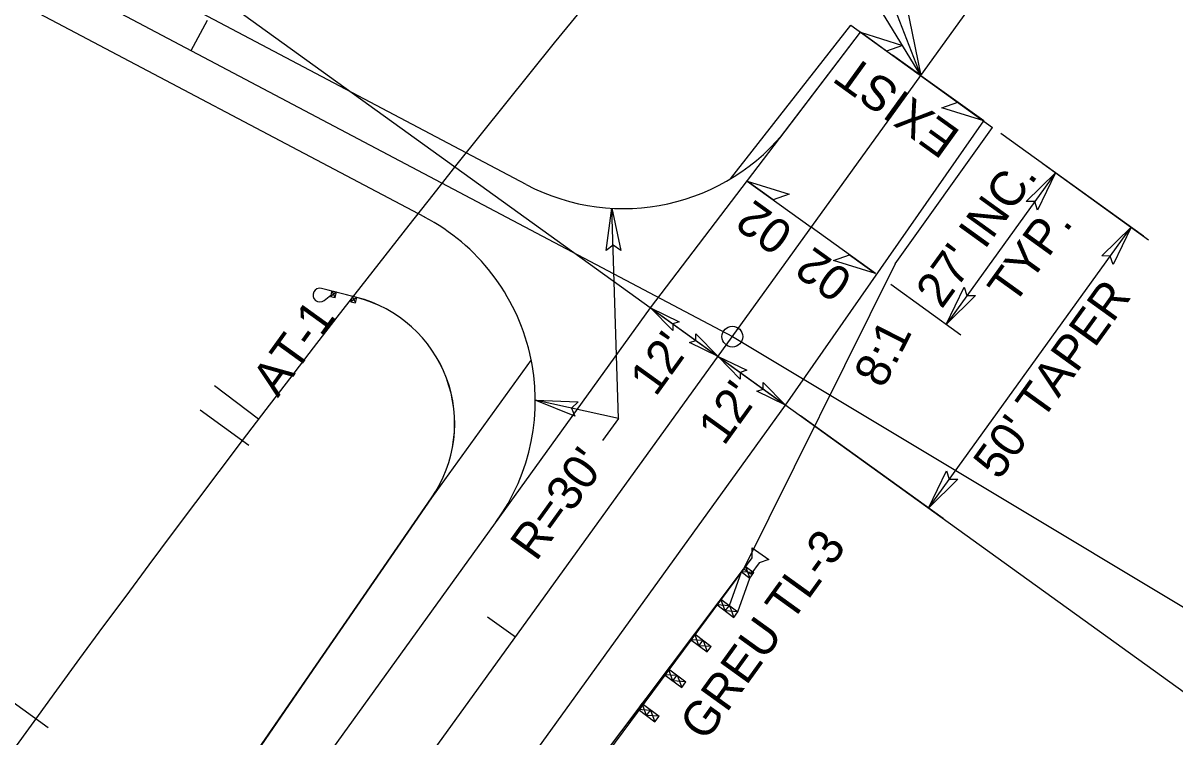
# Model space of a CAD drawing. Extents: x 2189281 to 2191267, y 386656 to 389012.
# Drawn here: x 2190394.2 to 2190560.4, y 388056.4 to 388159.5 of the extents above; entities that cross this region are included whole.
import ezdxf

# ---------------------------------------------------------------- set-up
doc = ezdxf.new("R2010")
doc.units = 0
for name, color, linetype in [('Prop Conc Shoulder Berm Gutter', 7, 'Continuous'), ('Prop Dimension', 7, 'Continuous'), ('Prop Dimension Text', 7, 'Continuous'), ('Prop DSN Text', 7, 'Continuous'), ('Prop EOT', 7, 'Continuous'), ('Prop Guardrail', 7, 'Continuous'), ('Prop Guardrail Anchor Unit CELL', 7, 'Continuous'), ('Prop Horizontal Alignment', 7, 'Continuous'), ('Prop Horizontal Alignment Station Label', 7, 'Continuous'), ('Prop Horizontal Alignment Tick Large', 7, 'Continuous'), ('Prop Horizontal Alignment Tick Small', 7, 'Continuous'), ('Prop Paved Shoulder', 7, 'Continuous'), ('Prop Superelevation  Arrow CELL', 7, 'Continuous'), ('Prop Superelevation Label', 7, 'Continuous'), ('Prop Terminator CELL', 7, 'Continuous'), ('Scratch_Level_5', 7, 'Continuous'), ('Scratch_Level_6', 7, 'Continuous')]:
    doc.layers.add(name, color=color, linetype=linetype)

msp = doc.modelspace()

# ---------------------------------------------------------------- linework, layer by layer
at = {"layer": 'Prop Conc Shoulder Berm Gutter'}
msp.add_line((2190437.14, 388067.73), (2190410.55, 388029.13), dxfattribs=at)
at = {"layer": 'Prop Dimension'}
for p, q in [((2190555.92, 388128.75), (2190535.33, 388143.6)), ((2190541.4, 388139.23), (2190556.63, 388128.24)), ((2190543.22, 388137.91), (2190527.43, 388116.01)), ((2190524.87, 388089.5), (2190554.12, 388130.05)), ((2190529.56, 388114.48), (2190519.46, 388121.76)), ((2190484.78, 388118.41), (2190504.24, 388104.37)), ((2190526.99, 388087.97), (2190506.41, 388102.81))]:
    msp.add_line(p, q, dxfattribs=at)
at = {"layer": 'Prop Dimension Text'}
for q in [(2190479.19, 388132.78), (2190468.12, 388105.07), (2190477.85, 388099.25)]:
    msp.add_line((2190480.16, 388102.45), q, dxfattribs=at)
at = {"layer": 'Prop DSN Text'}
msp.add_line((2190523.75, 388151.95), (2190443.96, 388359.41), dxfattribs=at)
at = {"layer": 'Prop EOT'}
for p, q in [((2190466.8, 388136.22), (2190376.83, 388183.79)), ((2190371.69, 388174.06), (2190452.14, 388131.53)), ((2190513.68, 388159.22), (2190534.13, 388144.46)), ((2190484.78, 388118.41), (2190515.08, 388158.2)), ((2190503.44, 388142.91), (2190515.08, 388158.2)), ((2190192.31, 387712.87), (2190484.78, 388118.41))]:
    msp.add_line(p, q, dxfattribs=at)
msp.add_lwpolyline([(2190181.76, 387658.83), (2190211.78, 387698.83), (2190504.24, 388104.37), (2190532.84, 388145.39)], dxfattribs=at)
for centre, start, end in [((2190480.83, 388162.74), 242.1321, 322.7007), ((2190438.12, 388105), 324.2018, 62.1321)]:
    msp.add_arc(centre, 30, start, end, dxfattribs=at)
at = {"layer": 'Prop Guardrail'}
msp.add_lwpolyline([(2190453.17, 388090.99), (2190411.02, 388029.82), (2190409.78, 388028.09)], dxfattribs=at)
msp.add_arc((2190437.67, 388101.68), 18.83, 325.3973, 75.5272, dxfattribs=at)
at = {"layer": 'Prop Guardrail Anchor Unit CELL'}
for p, q in [((2190438.95, 388120.79), (2190437.28, 388121.22)), ((2190438.75, 388120.84), (2190438.55, 388120.06)), ((2190438.75, 388120.84), (2190438.67, 388120.5)), ((2190438.75, 388120.84), (2190438.67, 388120.5)), ((2190439.43, 388120.67), (2190438.75, 388120.84)), ((2190438.75, 388120.84), (2190439.23, 388119.89)), ((2190438.88, 388120.81), (2190439.01, 388120.78)), ((2190438.88, 388120.81), (2190439.01, 388120.78)), ((2190442.38, 388119.91), (2190438.95, 388120.79)), ((2190437.66, 388119.49), (2190438.6, 388120.25)), ((2190439.43, 388120.67), (2190438.55, 388120.06)), ((2190438.55, 388120.06), (2190439.23, 388119.89)), ((2190439.23, 388119.89), (2190439.43, 388120.67)), ((2190441.7, 388120.08), (2190441.5, 388119.3)), ((2190442.38, 388119.91), (2190441.5, 388119.3)), ((2190441.5, 388119.3), (2190442.18, 388119.13)), ((2190442.38, 388119.91), (2190441.7, 388120.08)), ((2190441.7, 388120.08), (2190442.18, 388119.13)), ((2190442.18, 388119.13), (2190442.38, 388119.91)), ((2190499.45, 388082.32), (2190499.44, 388083.78)), ((2190499.44, 388083.78), (2190501.83, 388082.05)), ((2190498.25, 388080.66), (2190499.45, 388082.32)), ((2190498.47, 388081.08), (2190499.67, 388080.18)), ((2190498.47, 388081.08), (2190499.07, 388079.38)), ((2190500.44, 388081.6), (2190499.24, 388079.94)), ((2190501.83, 388082.05), (2190500.44, 388081.6)), ((2190470.07, 388043.32), (2190498.17, 388080.68)), ((2190496.15, 388075.44), (2190497.87, 388080.28)), ((2190497.37, 388074.52), (2190499.07, 388079.38)), ((2190497.87, 388080.28), (2190499.07, 388079.38)), ((2190499.67, 388080.18), (2190497.87, 388080.28)), ((2190498.74, 388080.3), (2190498.25, 388080.66)), ((2190499.24, 388079.94), (2190498.74, 388080.3)), ((2190499.07, 388079.38), (2190499.67, 388080.18)), ((2190499.07, 388079.38), (2190499.37, 388079.78)), ((2190494.92, 388076.37), (2190497.37, 388074.52)), ((2190495.55, 388074.65), (2190494.92, 388076.37)), ((2190494.32, 388075.57), (2190496.77, 388073.72)), ((2190494.32, 388075.57), (2190496.15, 388075.44)), ((2190495.55, 388074.65), (2190496.15, 388075.44)), ((2190497.37, 388074.52), (2190495.55, 388074.65)), ((2190496.15, 388075.44), (2190496.77, 388073.72)), ((2190496.77, 388073.72), (2190497.37, 388074.52)), ((2190491.14, 388071.33), (2190493.53, 388069.53)), ((2190491.74, 388069.63), (2190491.14, 388071.33)), ((2190490.54, 388070.53), (2190492.93, 388068.73)), ((2190490.54, 388070.53), (2190492.34, 388070.43)), ((2190491.74, 388069.63), (2190492.34, 388070.43)), ((2190493.53, 388069.53), (2190491.74, 388069.63)), ((2190492.34, 388070.43), (2190492.93, 388068.73)), ((2190492.93, 388068.73), (2190493.53, 388069.53)), ((2190487.35, 388066.29), (2190489.86, 388064.41)), ((2190488, 388064.55), (2190487.35, 388066.29)), ((2190486.75, 388065.49), (2190489.26, 388063.61)), ((2190486.75, 388065.49), (2190488.6, 388065.35)), ((2190488, 388064.55), (2190488.6, 388065.35)), ((2190489.86, 388064.41), (2190488, 388064.55)), ((2190488.6, 388065.35), (2190489.26, 388063.61)), ((2190489.26, 388063.61), (2190489.86, 388064.41)), ((2190482.96, 388060.46), (2190483.56, 388061.26)), ((2190483.56, 388061.26), (2190485.99, 388059.43)), ((2190484.18, 388059.55), (2190483.56, 388061.26)), ((2190482.96, 388060.46), (2190485.39, 388058.63)), ((2190482.96, 388060.46), (2190484.78, 388060.34)), ((2190484.18, 388059.55), (2190484.78, 388060.34)), ((2190485.99, 388059.43), (2190484.18, 388059.55)), ((2190484.78, 388060.34), (2190485.39, 388058.63)), ((2190485.39, 388058.63), (2190485.99, 388059.43))]:
    msp.add_line(p, q, dxfattribs=at)
msp.add_ellipse((2190437.03, 388120.26), major_axis=(-0.248, -0.961), ratio=0.995379, start_param=3.141593, end_param=7.214552, dxfattribs=at)
at = {"layer": 'Prop Horizontal Alignment'}
for p, q in [((2189529.37, 386773.11), (2190699.23, 388395.27)), ((2190330.06, 388202.3), (2190496.57, 388114.25))]:
    msp.add_line(p, q, dxfattribs=at)
msp.add_arc((2192257.95, 386708.79), 2300, 135.25499, 144.20184, dxfattribs=at)
at = {"layer": 'Prop Horizontal Alignment Station Label'}
msp.add_lwpolyline([(2190496.57, 388114.25), (2190600.88, 388051.67), (2190673.04, 388153)], dxfattribs=at)
msp.add_circle((2190496.57, 388114.25), 1.5, dxfattribs=at)
at = {"layer": 'Prop Horizontal Alignment Tick Large'}
msp.add_line((2190428.18, 388102.33), (2190421.81, 388107.17), dxfattribs=at)
at = {"layer": 'Prop Horizontal Alignment Tick Small'}
for p, q in [((2190418.46, 388155.55), (2190420.8, 388159.97)), ((2190523.75, 388151.95), (2190519.7, 388154.87)), ((2190465.26, 388070.84), (2190461.21, 388073.76))]:
    msp.add_line(p, q, dxfattribs=at)
at = {"layer": 'Prop Paved Shoulder'}
for p, q in [((2190496.28, 388137.02), (2190513.68, 388159.22)), ((2190520.07, 388124.74), (2190534.13, 388144.46)), ((2190520.07, 388124.74), (2190498.17, 388080.68)), ((2190498.17, 388080.68), (2190457.5, 388025.89))]:
    msp.add_line(p, q, dxfattribs=at)
msp.add_lwpolyline([(2190467.53, 388110.91), (2190453.17, 388090.99), (2190424.64, 388049.58)], dxfattribs=at)
at = {"layer": 'Prop Superelevation  Arrow CELL'}
for p, q in [((2190515.08, 388158.2), (2190524.82, 388151.18)), ((2190532.84, 388145.39), (2190523.11, 388152.41)), ((2190498.72, 388136.71), (2190507.96, 388130.05)), ((2190517.23, 388123.38), (2190507.96, 388130.05))]:
    msp.add_line(p, q, dxfattribs=at)
for points in [[(2190515.08, 388158.2), (2190521.12, 388156.31), (2190518.84, 388155.49)], [(2190532.84, 388145.39), (2190526.81, 388147.28), (2190529.09, 388148.1)], [(2190498.72, 388136.71), (2190504.75, 388134.83), (2190502.47, 388134.01)], [(2190517.23, 388123.38), (2190511.19, 388125.26), (2190513.48, 388126.08)]]:
    msp.add_lwpolyline(points, close=True, dxfattribs=at)
at = {"layer": 'Prop Terminator CELL'}
for points in [[(2190519.19, 388174.32), (2190523.75, 388151.95), (2190511.81, 388171.58), (2190516.58, 388170.35)], [(2190538.98, 388133.76), (2190543.22, 388137.91), (2190540.63, 388132.53), (2190540.22, 388133.75)], [(2190478.34, 388126.67), (2190479.19, 388132.78), (2190480.47, 388126.7), (2190479.36, 388127.44)], [(2190549.88, 388125.9), (2190554.12, 388130.05), (2190551.52, 388124.67), (2190551.11, 388125.89)], [(2190531.67, 388120.17), (2190527.43, 388116.01), (2190530.03, 388121.39), (2190530.43, 388120.18)], [(2190487.97, 388115.15), (2190484.78, 388118.41), (2190488.91, 388116.41), (2190487.98, 388116.1)], [(2190487.97, 388115.15), (2190484.78, 388118.41), (2190488.91, 388116.41), (2190487.98, 388116.1)], [(2190491.31, 388114.65), (2190494.51, 388111.39), (2190490.37, 388113.39), (2190491.3, 388113.7)], [(2190497.7, 388108.13), (2190494.51, 388111.39), (2190498.65, 388109.4), (2190497.71, 388109.08)], [(2190501.04, 388107.63), (2190504.24, 388104.37), (2190500.1, 388106.37), (2190501.04, 388106.68)], [(2190501.04, 388107.63), (2190504.24, 388104.37), (2190500.1, 388106.37), (2190501.04, 388106.68)], [(2190473.84, 388102.75), (2190468.12, 388105.07), (2190474.33, 388104.83), (2190473.34, 388103.93)], [(2190529.11, 388093.65), (2190524.87, 388089.5), (2190527.47, 388094.88), (2190527.87, 388093.66)]]:
    msp.add_lwpolyline(points, close=True, dxfattribs=at)
at = {"layer": 'Scratch_Level_5'}
for p, q in [((2190332.29, 388228.38), (2190604.85, 388031.82)), ((2190419.74, 388103.67), (2190426.81, 388098.57)), ((2190343.76, 388096.82), (2190397.82, 388057.83))]:
    msp.add_line(p, q, dxfattribs=at)
at = {"layer": 'Scratch_Level_6'}
msp.add_line((2190442.38, 388119.9), (2190437.28, 388121.21), dxfattribs=at)
for points in [[(2190396.39, 388009.55), (2190411.01, 388029.82), (2190453.16, 388090.99)], [(2190428.85, 387986.14), (2190443.47, 388006.41), (2190470.08, 388043.31), (2190498.18, 388080.68)]]:
    msp.add_lwpolyline(points, dxfattribs=at)
msp.add_arc((2190437.67, 388101.68), 18.82, 325.3973, 75.5272, dxfattribs=at)

# ---------------------------------------------------------------- texts
at = {"layer": 'Prop Dimension Text'}
for s, rotation, p in [("27' INC.", 54.2018, (2190526.78, 388118.12)), ('TYP.', 54.2018, (2190537.17, 388118.63)), ("50' TAPER", 54.2018, (2190535.06, 388093.39)), ('8:1', 63.066, (2190518.36, 388106.62)), ("12'", 54.2018, (2190485.49, 388105.45)), ("12'", 54.2018, (2190495.35, 388098.35)), ("R=30'", 54.2019, (2190468.25, 388081.66))]:
    msp.add_text(s, height=5, rotation=rotation, dxfattribs=at).set_placement(p)
at = {"layer": 'Prop Guardrail Anchor Unit CELL'}
for s, p in [('AT-1', (2190430.98, 388105.33)), ('GREU TL-3', (2190492.7, 388055.63))]:
    msp.add_text(s, height=5, rotation=54.2018, dxfattribs=at).set_placement(p)
at = {"layer": 'Prop Superelevation Label'}
for s, p in [('EXIST', (2190529.69, 388143.79)), ('02', (2190505.63, 388129.83)), ('02', (2190514.22, 388123.04))]:
    msp.add_text(s, height=5, rotation=144.227, dxfattribs=at).set_placement(p)

doc.saveas('drawing.dxf')
